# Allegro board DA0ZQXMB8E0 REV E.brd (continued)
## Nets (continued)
Pads without a net: C6 2; C7 1 2; C9 2; C10 1; C11 1; C12 1; C13 1; C15 1 2; C16 1; C17 2; C18 1; C19 1 2; C20 1 2; C21 1; C23 1 2; C28 1 2; C31 1; C32 1; C33 2; C40 1 2; C80 2; C82 1 2; C84 1 2; C110 2; C111 1 2; C122 1 2; C123 1 2; C124 1 2; C125 1 2; C126 1 2; C127 1 2; C128 1 2; C129 1 2; C130 1 2; C131 1 2; C132 1 2; C133 1 2; C134 1 2; C135 1 2; C136 1 2; C137 1 2; C138 1 2; C139 2; C140 1 2; C141 1 2; C142 1 2; C143 1 2; C144 1 2; C145 1 2; C146 1 2; C147 1 2; C148 1 2; C152 1 2; C153 1 2; C154 1 2; C156 1 2; C157 1; C158 1 2; C160 1 2; C161 2; C162 2; C163 2; C164 1 2; C165 1 2; C166 2; C167 1 2; C168 1 2; C169 1 2; C170 1; C171 1; C172 1 2; C173 1 2; C174 1 2; C175 2; C176 2; C177 2; C178 1 2; C182 1 2; C183 1 2; C185 1 2; C186 1 2; C187 1 2; C188 2; C189 1; C190 1 2; C191 1 2; C192 1; C193 1; C194 1 2; C195 2; C197 2; C198 2; C199 1 2; C200 1 2; C201 1 2; C203 2; C204 1 2; C205 1 2; C206 2; C207 1 2; C208 2; C209 1 2; C210 1; C211 1 2; C212 1 2; C213 1 2; C214 1 2; C215 1 2; C216 1 2; C217 1 2; C218 1 2; C219 1 2; C220 1 2; C221 1 2; C222 1 2; C223 1 2; C224 2; C225 1 2; C226 2; C227 1 2; C228 1 2; C229 2; C230 2; C231 2; C232 2; C233 1 2; C234 2; C235 2; C236 2; C237 2; C238 2; C239 2; C240 1 2; C241 1 2; C242 2; C243 2; C244 1 2; C245 2; C246 1 2; C247 2; C248 2; C249 1 2; C250 2; C251 1 2; C252 2; C253 2; C254 2; C255 2; C256 2; C257 2; C258 1 2; C259 2; C260 2; C261 1 2; C262 2; C263 1 2; C264 2; C265 2; C266 2; C267 2; C268 2; C269 2; C270 1 2; C271 2; C272 1 2; C273 1 2; C274 2; C275 1 2; C276 1 2; C277 1 2; C278 1 2; C279 2; C280 1 2; C281 1; C282 2; C284 1 2; C285 2; C286 1 2; C287 1 2; C288 1 2; C289 1 2; C290 1 2; C291 1 2; C292 1; C293 1 2; C294 1; C295 1 2; C296 1 2; C297 1 2; C298 1 2; C299 2; C300 2; C301 2; C302 2; C305 2; C306 2; C307 2; C308 2; C309 1; C310 1 2; C311 1 2; C312 2; C313 1 2; C314 1 2; C315 1 2; C316 1 2; C317 1 2; C318 1 2; C319 1; C320 1; C322 2; C323 2; C324 1; C325 2; C326 2; C328 2; C329 2; C330 2; C331 2; C332 2; C333 1; C334 2; C335 1 2; C336 2; C337 1 2; C338 2; C339 1; C340 1; C341 1 2; C342 1 2; C343 1 2; C344 1 2; C345 1; C346 2; C347 1 2; C348 1 2; C349 2; C350 1 2; C351 1 2; C352 1 2; C353 2; C354 1; C356 2; C357 1 2; C358 1 2; C359 2; C360 1 2; C369 1; C370 1; C371 1 2; C372 1 2; C373 1 2; C374 1 2; C376 1 2; C391 1; C392 1; C394 1; C398 2; C404 1 2; C405 1 2; C407 1 2; C408 1 2; C409 1 2; C410 1 2; C411 1 2; C412 2; C415 1 2; C419 2; C420 1; C421 2; C422 1 2; C425 1 2; C426 1 2; C427 2; C428 2; C429 1 2; C430 1 2; C431 1 2; C432 2; C433 1 2; C434 1 2; C435 1 2; C436 2; C437 1; C438 1; C439 1 2; C440 1 2; C441 1 2; C442 1 2; C443 1 2; C444 1 2; C445 1 2; C447 2; C448 1; C449 2; C450 1; C451 2; C452 1 2; C453 1 2; C456 1 2; C457 2; C458 1 2; C459 1 2; C462 2; C463 1; C464 2; C465 1 2; C466 2; C469 1 2; C470 1 2; C471 1 2; C472 1 2; C473 1 2; C474 1; C475 1 2; C476 1; C477 1 2; C478 2; C479 1 2; C480 1; C481 1; C482 1 2; C483 1 2; C484 1 2; C485 1 2; C486 1 2; C487 1 2; C488 1 2; C489 2; C490 2; C491 1 2; C492 1 2; C493 1 2; C494 1 2; C495 1 2; C496 1 2; C498 1 2; C499 1 2; C500 1 2; C501 1 2; C502 1 2; C503 1 2; C504 1 2; C505 1 2; C507 1 2; C508 1 2; C509 1 2; C510 1 2; C511 1 2; C512 1 2; C513 1 2; C514 1 2; C515 1 2; C516 1 2; C517 1 2; C518 1 2; C519 1 2; C520 1 2; C522 1 2; C523 2; C524 1 2; C525 1; C526 1 2; C527 2; C528 1 2; C529 1 2; C530 1 2; C531 1 2; C532 1 2; C533 1 2; C534 2; C535 2; C536 1 2; C537 1 2; C538 1 2; C539 1 2; C540 1 2; C541 1 2; C542 1 2; C543 1 2; C544 1 2; C545 1 2; C546 1 2; C547 2; C548 1 2; C549 1 2; C550 1 2; C551 1; C553 1 2; C554 1 2; C555 2; C556 1 2; C557 1 2; C558 1 2; C559 2; C560 1 2; C561 1 2; C562 1 2; C563 1 2; C564 1 2; C565 1 2; C566 2; C567 2; C568 2; C569 1; C570 2; C571 1; C572 1; C573 1 2; C576 1 2; C577 1; C578 1; C579 1 2; C580 1 2; C581 1 2; C582 1 2; C692 1 2; CN6 1 4 5 6 9 10 12 15 18 21 24 25 26 27 30 31 34 36 39 40 43 46 49 51 52 54 55 56 58 59 60; CN7 1 2 3 5 6 7 9 12 15 24 25 28 29 37 38 39 40 41 42 43 44; CN8 1 2 3 5 7 9 18 19 20 23 24 25 26 27 28 29 30 31 32 33 34 35 36 37 38 39 40 41 43 45; CN10 5; CN11 1 2 3 4 5 6 7 8 9 12 14 15 18 19 20 22 24 25 26 30 31 32; CN12 11 12; CN13 1 2 3 4 5 6 7 10; CN14 3 4 5 6 7 8 9 11 12 13 14 15 16 17 20 21 23 24 26 27 28; CN15 3 5; CN17 1 4 9 10; CN18 2 5 11 17 20 21 22 23; CP6 1 2 3 4 5 7 8; CP7 1 3 4 5 6 7; CP8 1 2 3 4 5 6 7; CP9 1 2 3 4 5 6 7 8; CP10 1 2 3 4 5 6 7; CP11 1 2 3 4 5 6 7 8; D6 1; D7 1 2; D8 1 2; D9 1; D11 1; D13 1; D14 1; D15 1; D16 1; D17 2; D19 2; D20 1; D21 2; D22 1 2; D23 1 2; D24 1 2; D25 2; D26 2; D27 1 2; D28 1 2; HOLE7 1 2 3 4 5 6 7 8 9; HOLE10 2 3 4 5 6 7 8 9; HOLE15 5 7; HOLE16 5 7; HOLE17 5 7; JDIM6 3 8 9 11 13 19 31 37 43 49 55 76 82 88 100 106 112 118 122 124 128 134 136 138 144 150 156 161 167 168 173 178 179 184 185 187 189 195 196 199 200 203 204 205 206; JP6 1 2; JP7 2; JP8 1; JP9 1 2; JP11 2; JP12 1 2; JP13 2; JP14 1 2; JP15 2; JP16 2; JP17 1 2; JP18 1 2; L6 2; L9 1; L10 1; L11 1 2; L12 1 2; L15 1 2; L16 1; L17 1; L18 1; L19 1; L21 1 2; L22 1 2; MR6 2 3; PC6 1 2; PC7 1 2; PC8 1 2; PC9 2; PC11 1 2; PC12 1 2; PC13 2; PC14 2; PC15 1 2; PC16 2; PC17 2; PC18 1 2; PC19 1 2; PC20 1 2; PC21 2; PC22 1; PC23 1; PC24 1; PC25 1; PC26 1; PC27 1; PC29 1 2; PC30 1 2; PC31 2; PC32 1; PC34 1; PC35 2; PC37 1 2; PC38 1 2; PC41 2; PC42 1 2; PC43 2; PC44 1 2; PC47 2; PC49 1 2; PC52 1 2; PC53 2; PC55 1 2; PC58 1; PC59 2; PC60 2; PC61 1 2; PC62 1; PC64 2; PC65 2; PC66 2; PC67 1; PC68 1 2; PC69 2; PC70 2; PC73 2; PC74 1 2; PC76 1 2; PC77 2; PC78 2; PC82 1 2; PC83 1 2; PC86 1 2; PC87 2; PC88 1; PC90 2; PC91 1 2; PC92 1 2; PC93 1 2; PC95 2; PC97 2; PC98 2; PC99 1 2; PC100 2; PC101 2; PC102 2; PC103 1; PC104 2; PC105 1 2; PC107 1 2; PC109 1 2; PC110 1 2; PC111 1; PC112 1; PC113 1 2; PC114 1; PC115 2; PC116 2; PC117 2; PC119 2; PC121 2; PC122 2; PC123 2; PC126 1 2; PC128 1; PC129 1 2; PC130 2; PC132 1; PC133 2; PC134 1 2; PC135 1; PC136 1; PC137 1 2; PC139 2; PC140 1 2; PC141 2; PC142 2; PC144 1 2; PC145 1 2; PC146 1 2; PC147 1; PC149 2; PC150 1; PC151 2; PC153 2; PC154 1 2; PC155 2; PC157 2; PC158 2; PC159 2; PC160 1; PC161 1; PC162 2; PC163 2; PC164 1 2; PC168 1 2; PC169 1 2; PC170 1 2; PC171 1; PC172 1; PC173 1; PC174 1 2; PC176 1 2; PC177 2; PC178 1; PC180 2; PC181 2; PC182 1 2; PC183 1; PC185 2; PC186 1; PC187 2; PC188 1; PC189 1 2; PC190 1 2; PC191 1 2; PC192 1; PC193 1 2; PC194 1 2; PD6 1 2; PD8 1 2 3; PD9 1; PD10 2 3; PJ6 3; PL7 1 2; PL10 1; PL11 1 2; PL12 1 2; PL13 2 4; PL16 2; PQ6 1 2; PQ7 1 3; PQ8 1 2 3; PQ9 1 2 3; PQ10 1 2 3; PQ11 1 2 3; PQ12 1 2; PQ13 1 2 3; PQ14 1 3; PQ15 1 2; PQ16 1 3; PQ17 1 2 3; PQ18 1 2 3; PQ19 1 2 3; PQ20 1 3; PQ21 1; PQ22 1 2; PQ23 1 3; PQ24 3; PQ25 1 3 4 5; PQ26 1 3 4 5; PQ27 1; PQ28 1 3; PQ29 1; PQ30 1 2; PQ31 1; PQ32 1 2 3 4 5; PQ33 1; PQ34 1 2 3 5; PQ35 1 3; PQ36 1 2 3 4 5; PQ37 1 2 3 4 5; PQ38 1 3; PQ39 1 2 3 4 5; PQ40 1 3 4; PQ41 1 3 4 5; PQ42 1 3 4 5; PQ43 1 2 3; PQ44 1 3; PQ45 1 2; PQ46 1 2; PQ48 1 3 4 5; PQ49 1 3 4 5; PQ50 1 3; PQ51 5; PQ52 1 3; PQ53 1 4; PR6 2; PR8 1; PR9 2; PR10 1 2; PR11 1 2; PR12 2; PR13 1 2; PR16 2; PR17 2; PR18 1 2; PR20 1; PR21 2; PR22 1 2; PR23 1 2; PR24 1 2; PR25 1 2; PR26 1 2; PR28 1 2; PR29 1 2; PR30 1 2; PR31 1 2; PR32 1 2; PR33 1 2; PR34 1 2; PR35 1 2; PR37 2; PR38 2; PR39 1; PR40 1 2; PR41 1 2; PR42 1 2; PR43 1 2; PR44 1; PR45 1; PR46 1 2; PR47 1 2; PR48 2; PR49 1; PR50 1 2; PR51 2; PR53 1 2; PR54 1; PR55 1 2; PR56 1; PR57 1 2; PR58 1; PR62 2; PR63 1 2; PR64 1; PR68 1; PR69 1; PR73 1; PR76 1 2; PR80 2; PR81 2; PR83 1; PR84 2; PR85 2; PR86 2; PR91 2; PR93 1; PR94 1; PR95 2; PR96 2; PR97 1; PR98 2; PR99 2; PR101 1; PR102 2; PR103 1; PR104 1 2; PR105 2; PR107 1; PR108 1; PR109 1; PR110 2; PR113 1 2; PR114 1 2; PR115 1 2; PR116 1; PR117 1; PR118 2; PR119 1 2; PR120 1 2; PR121 1; PR128 2; PR130 2; PR131 1; PR134 1; PR137 2; PR138 2; PR139 2; PR140 1; PR141 2; PR143 1 2; PR147 1 2; PR153 1 2; PR156 1; PR159 2; PR160 1 2; PR161 1; PR163 1 2; PR169 1 2; PR170 1 2; PR171 1 2; PR172 2; PR173 1; PR174 1 2; PR175 1; PR177 1 2; PR178 1 2; PR179 1; PR180 1; PR181 1; PR183 2; PR184 1; PR185 2; PR198 1; PR199 2; PR202 1 2; PR205 2; PR206 1; PR208 2; PR213 2; PR215 1; PR218 2; PR220 2; PR225 2; PR226 1; PR228 1; PR229 2; PR230 1; PR232 2; PR233 2; PR234 1 2; PR235 1 2; PU6 1 6 9 10 11 13 14 15 20; PU7 21 22 33 34 35 37 38 40 41 42; PU10 2 3 5 6 8 12 13 14 15 16; PU13 4 6; PU16 1 2 5 6 11; PU17 2 14; PU18 1 5 6; Q6 2 5 6; Q8 1 3; Q9 1; Q10 1 4 6; Q12 1 2; Q13 1 2 3; Q14 2 3 5 6; Q15 1 2; Q17 2 4 5; Q18 1; Q19 2; Q20 1; Q21 2 3; Q22 1; Q23 2; Q24 2; Q25 2; Q26 1 4 6; Q27 2 3; Q28 2; Q30 1; Q33 1 2 3; Q35 1 2 3; Q38 1; Q40 1 3; Q41 3; Q42 3; Q43 3; Q44 2 5; Q45 1 2; R7 1 2; R9 2; R10 1 2; R11 2; R30 1 2; R38 2; R39 1; R40 1 2; R42 2; R47 1; R48 1 2; R49 1 2; R56 1 2; R59 1 2; R60 1; R61 1 2; R64 1 2; R65 2; R67 1; R69 1; R78 1; R82 1 2; R83 1; R87 2; R88 1 2; R89 1 2; R91 1; R92 1; R93 2; R94 2; R95 1; R96 2; R97 1; R98 1; R99 1 2; R101 1 2; R102 1; R103 1; R104 1 2; R105 1; R106 2; R107 1 2; R108 1 2; R109 1 2; R110 1 2; R111 1 2; R112 1 2; R113 1; R114 1; R115 1 2; R116 1 2; R117 2; R118 1; R119 1; R120 1 2; R121 1; R122 1 2; R123 1; R124 1; R126 1; R127 1 2; R128 1; R129 1; R134 2; R135 1 2; R137 1 2; R140 2; R141 2; R142 2; R143 1; R144 2; R145 1 2; R146 1; R147 2; R148 1 2; R149 1; R150 1 2; R151 2; R152 2; R153 2; R154 1; R155 1 2; R156 1; R157 2; R158 2; R159 2; R160 2; R161 1; R162 2; R163 1; R164 2; R165 2; R166 2; R167 1; R168 2; R169 1 2; R170 1 2; R171 2; R172 1; R173 1; R174 1; R176 2; R177 1 2; R178 2; R179 1 2; R180 2; R181 2; R182 2; R183 2; R184 2; R185 1 2; R186 2; R187 2; R188 2; R189 2; R190 2; R191 2; R192 2; R193 1 2; R197 2; R198 2; R199 2; R200 2; R201 2; R202 1; R205 2; R206 2; R207 1 2; R208 1 2; R211 2; R213 1; R214 1 2; R215 1 2; R217 1; R218 1; R219 1; R220 1; R222 2; R223 1; R224 1; R225 1; R230 1; R231 1 2; R232 2; R233 2; R234 1; R235 2; R236 1; R237 1; R238 2; R239 1 2; R242 1; R246 1 2; R247 1 2; R248 1; R249 1; R250 2; R251 1 2; R252 2; R253 1 2; R254 1; R255 2; R257 1; R258 1; R259 1; R260 1; R261 1 2; R262 1 2; R263 2; R264 1 2; R265 1 2; R266 1 2; R268 1; R269 1 2; R270 1 2; R271 1; R272 1; R273 1; R274 1; R275 2; R276 1 2; R277 1; R281 1; R284 1; R286 2; R288 1; R289 1; R290 2; R291 2; R292 2; R293 1; R294 2; R295 1; R296 1 2; R297 1; R300 1; R301 1; R302 2; R303 1; R306 2; R307 2; R308 2; R309 1; R310 1 2; R311 2; R313 1; R315 1 2; R316 2; R317 2; R318 1 2; R319 2; R320 1; R322 1; R328 1; R329 1; R330 1; R331 2; R332 2; R333 1 2; R334 2; R336 2; R345 1 2; R366 2; R369 1; R370 1; R371 1 2; R375 1 2; R376 2; R377 2; R378 2; R382 1 2; R383 1 2; R385 1 2; R386 1; R388 1 2; R389 1 2; R390 1 2; R391 1 2; R393 1 2; R394 1 2; R395 2; R396 2; R401 2; R404 1 2; R405 1 2; R406 1 2; R407 1 2; R408 1 2; R411 1 2; R412 1 2; R413 1 2; R414 2; R417 1 2; R420 1 2; R422 1; R423 1; R424 1 2; R425 1 2; R426 1; R427 1; R428 1; R433 2; R434 2; R435 1 2; R436 1; R437 1 2; R438 1 2; R439 1 2; R440 1 2; R441 1; R442 2; R443 1 2; R444 2; R445 2; R446 2; R448 1 2; R449 1 2; R451 1; R452 1 2; R453 2; R454 2; R455 1; R456 2; R457 1 2; R458 2; R459 2; R460 2; R461 1; R462 2; R463 1; R464 2; R465 1 2; R466 1; R467 2; R469 1; R470 2; R471 2; R472 1; R473 1 2; R474 1; R475 1 2; R476 1 2; R477 1; R478 2; R479 2; R480 1; R483 2; R485 1; R486 2; R487 2; R488 2; R489 2; R490 1; R491 2; R492 2; R493 1; R494 2; R495 2; R496 1; R497 2; R498 2; R499 1 2; R500 1; R501 1; R502 2; R503 1; R504 2; R505 2; R506 2; R507 1 2; R509 1; R510 2; R512 2; R514 1; R515 2; R517 2; R518 2; R519 1 2; R520 1; R522 1; R523 2; R525 2; R527 2; R528 1; R530 1; R531 2; R533 1; R534 2; R536 1; R537 1 2; R541 1; R543 1; R547 1; R549 1; R550 1; R552 1; R553 1; R554 1 2; R555 1 2; R556 2; R557 1 2; R558 2; R559 1 2; R560 1 2; R561 1 2; R562 2; R564 1 2; R565 2; R566 1; R567 2; R568 1 2; R570 1 2; R571 1; R573 1; R576 2; R577 1 2; R578 2; R579 2; R580 1 2; R582 2; R583 1 2; R585 1; R586 1; R587 1 2; R588 2; R593 2; R594 1 2; R595 2; R596 2; R597 2; R599 1 2; R600 1 2; R603 1 2; R604 1; R609 2; R610 1 2; R611 1; R613 2; R614 2; R615 1; R616 1; R617 2; R619 2; R621 2; R623 1; R625 2; R627 2; R631 2; R632 1 2; R633 1 2; R635 2; R650 2; R653 2; RP6 1 2 3 4 5 8 9 10; RP7 3 4 5 6 7 8 9 10; RV6 2; SW7 2 3; TP18 1; TP72 1; TP76 1; TP77 1; TP83 1; TP90 1; TP101 1; TP102 1; TP105 1; U6 2 4 5 6; U7 2 3 4 5; U8 1 3 4 8 10 11 12 13 14 15 18 19 22 24 25 26 28; U9 3 5; U10 4; U12 A1 A7 A8 A9 B1 B2 J8 J9 K1 K2 K3 K7 K8 L1 L2 L3 L7 L9 M1 M2 M3 R2 R3 R9 T1 T2 T3 T7 T9; U13 A1 A8 A9 B1 B2 J8 J9 K1 K2 K3 K7 K8 L1 L2 L3 L7 L9 M1 M2 M3 R2 R3 R9 T1 T2 T3 T7 T9; U14 A1 A8 A9 B1 B2 J8 J9 K1 K2 K3 K7 K8 L1 L2 L3 L7 L9 M1 M2 M3 R2 R3 R9 T1 T2 T3 T7 T9; U15 A1 A3 A8 A9 B1 B2 J8 J9 K1 K2 K3 K7 K8 L1 L2 L3 L7 L9 M1 M2 M3 R2 R3 R9 T1 T2 T3 T7 T9; U16 4 6 10 14 15; U17 2 3 4 5 11 12 14 15 16 18 20 23 24 25 26 30 38 41 42 43 44 45 46 48 49; U18 1 2 3 4; U19 1 2 3 4 5; U24 4 5 6; U25 1 2 4 6 10 68 69 70 71 100 125 127 128; U26 A1 A3 A8 A9 B1 B2 J8 J9 K1 K2 K3 K8 L1 L2 L3 L7 L9 M1 M2 M3 R2 R3 R9 T1 T2 T3 T7 T9; U27 A1 A8 A9 B1 B2 J8 J9 K1 K2 K3 K8 L1 L2 L3 L7 L9 M1 M2 M3 R2 R3 R9 T1 T2 T3 T7 T9; U28 A3 A4 A24 A28 A36 A44 A47 AA1 AA63 AC2 AC61 AC62 AD63 AE5 AE8 AF1 AF9 AG1 AH28 AH42 AH44 AH46 AJ43 AJ45 AJ47 AK23 AK62 AK63 AL1 AL17 AL26 AL45 AL46 AM1 AM52 AN36 AN39 AN40 AN42 AN43 AN45 AN46 AP1 AP36 AP38 AP39 AR5 AR15 AR48 AT1 AT2 AT13 AT43 AT46 AU1 AU12 AU43 AU44 AV2 AV3 AV8 AV10 AV42 AV43 AV44 AW2 AW3 AW4 AW33 AW34 AW37 AW39 AW42 AW43 AW49 AW50 AW51 AW53 AY2 AY3 AY4 AY6 AY8 AY26 AY33 AY40 AY41 B24 B26 B28 B37 B43 C1 C24 C25 C27 C28 C33 C39 C45 C46 C47 C48 D2 D5 D6 D8 D9 D17 D18 D21 D23 D25 D26 D27 D43 D47 E5 E17 E18 E23 E25 E27 E43 E45 E47 F8 F18 F22 F24 F26 F28 F42 F46 F48 F62 G3 G5 G6 G8 G22 G23 G25 G27 G43 G45 G47 H5 H6 H22 H23 J3 J4 J5 J6 J11 J22 J23 K1 L61 N3 N5 P2 P62 P63 R6 R7 R8 T1 U8 U61 V1 V2 Y2 Y63; U29 A1 A8 A9 B1 B2 J8 J9 K1 K2 K3 K8 L1 L2 L3 L7 L9 M1 M2 M3 R2 R3 R9 T1 T2 T3 T7 T9; U30 15 16 21 22; U31 1 2 5; U32 A1 A2 A8 A9 B1 B2 J8 J9 K1 K2 K3 K8 L1 L2 L3 L7 L9 M1 M2 M3 R2 R3 R9 T1 T2 T3 T7 T9; U33 1 5; U34 2; U35 2; U36 28 29 31 32 33; U37 1 5; U38 3 5; U39 1 2 5; U40 1 2 3 6 7 8; Y7 2 3; Y8 2 4; Y9 1 2 3 4

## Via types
v1: diameter 0.508, hole 0.254, TOP to BOTTOM, 78 vias
v2: diameter 0.61, hole 0.356, TOP to BOTTOM, 21 vias
v3: diameter 0.66, hole 0.33, TOP to BOTTOM, 16 vias
v4: diameter 0.66, hole 0.254, TOP to BOTTOM, 19 vias

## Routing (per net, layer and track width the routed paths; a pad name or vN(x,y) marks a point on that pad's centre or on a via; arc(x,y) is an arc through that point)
5VPCU_AGND: length 1.3
  TOP w0.381: PC63.1 58.37,44.15 58.72,44.49
  BOTTOM w0.203: PU16.14 55.57,44.96 55.77,44.76 55.85,44.76 55.9,44.71 55.92,44.71 55.97,44.65 56,44.65 56.02,44.63
+1.05V_DCPSUS1: length 0.6
  TOP w0.102: C231.1 131.14,82.31
+1.05V_DCPSUS2: length 1.3
  TOP w0.254: C232.1 R238.1
+1.5VA: length 1.7
  TOP w0.508: 228.71,54.5 228.72,54.51 C302.1 C301.1
+3V_PCH_ME: length 2.3
  BOTTOM w0.508: 142.84,118.65 142.84,120.32 142.75,120.41 C420.2
+3V_RTC: length 3.2
  BOTTOM w0.508: 218.43,125.55 220.15,125.55 C412.1 ; C447.1 R526.1
+A3VPCU: length 2.9
  BOTTOM w0.203: 201.82,116.17 200.58,116.17
  BOTTOM w0.508: L17.2 198.24,117.11 C424.1
+V1.05S_AIDLE: length 1.2
  BOTTOM w0.254: 126.87,95.48 v1(126.87,96.15) 126.62,96.15 U28.N8
  vias: v1(118.81,100.69) v1(119.5,100.69)
+V1.05S_APLLOPI:
  vias: v1(104.62,91.14) v1(104.99,91.64) v1(129.78,88.28) v1(130.6,88.28)
+V1.05S_ASATA3PLL: length 5.8
  BOTTOM w0.178: 118.36,93.78 119.3,93.78 119.33,93.82 119.75,93.82
  BOTTOM w0.254: 118.36,93.78 118.23,93.78 118.08,93.93 116.12,93.93 115.51,94.54 115.51,94.87 115.1,95.29 R539.2
+V1.05S_AXCK_LCPLL: length 4
  BOTTOM w0.254: 118.51,89.69 118.51,89.59 119.11,88.99
  BOTTOM w0.508: 118.51,89.69 118.51,89.79 116.45,91.85
+V3.3M_PSPI: length 3
  BOTTOM w0.254: 130.21,95.93 130.44,95.93 130.66,96.15
  BOTTOM w0.381: 104.51,102.36 R522.2 106.16,103.13
+V3.3S_VCCPCORE:
  vias: v1(111.62,101.93) v1(112.08,103.02) v1(112.08,102.36) v1(129.71,94.56)
+V3.3S_VCCPTS: length 1.7
  TOP w0.381: C208.1 100.08,90.84 99.69,91.24
+VCCIOA_OUT: length 0.6
  BOTTOM w0.254: U28.E20 121.96,89.1 121.96,88.8
VSS_SENSE: length 1.4
  TOP w0.254: PC43.1 72.06,64.73 72.08,64.75 PR97.2
671_SW:
  vias: v2(53.13,53.01) v2(53.15,52.12) v2(53.18,50.93) v2(53.18,49.86) v2(53.23,48.8) v2(54.09,53.93) v2(54.17,48.82) v2(54.83,54.43) v2(55.08,48.82)
671PG: length 1.8
  BOTTOM w0.203: PU16.4 51.67,45.55 51.08,46.14 51.08,46.15
24737_BM#: length 1.6
  TOP w0.305: 78.07,46.72 77.56,46.2 PQ31.2
24737_BST: length 2.6
  BOTTOM w0.279: 84.34,44.35 84.34,44.6 83.79,45.16 82.96,45.16 82.9,45.1 PU17.17
24737_DH: length 1.1
  BOTTOM w0.279: PU17.18 83.13,44.6 83.18,44.55 83.33,44.55
24737_DL: length 1.1
  BOTTOM w0.508: PQ50.4 87.18,50.66 86.85,50.32 86.81,50.32
24737_VCC: length 0.5
  BOTTOM w0.279: PC188.2 83.86,41.81
51216_REFIN: length 0.7
  TOP w0.208: PC33.1 229.32,76.25 228.79,76.25
51624_ALERT#: length 2
  TOP w0.198: PU7.32 79.9,61.05 80.23,60.73 PR108.2
51624_CLK: length 2
  TOP w0.198: PR107.2 79.5,60.57 PU7.31
51624_CSN2: length 1
  BOTTOM w0.198: PC156.2 PR204.2
51624_CSP1: length 1.2
  BOTTOM w0.198: PC152.1 74.12,68.24 73.91,68.02 73.33,68.02 PR201.1
51624_CSP2: length 2.4
  BOTTOM w0.198: PC156.1 PR204.1
  BOTTOM w0.305: PC157.1 72.21,65.51 72.98,65.51 PC156.1
51624_DROOP: length 5
  TOP w0.198: PU7.25 76.76,62.19 76.52,61.95
  TOP w0.305: 74.16,59.33 74.39,59.1 PC50.1 ; PC46.1 76.52,61.95
  TOP w0.381: PC50.1 75.09,58.9 PR111.1
51624_PWM1_R: length 0
  BOTTOM w0.198: 83.56,69.12 83.56,69.17
+AZA_VDD: length 1.4
  TOP w0.508: R256.1 v1(219.96,59.72)
+SMDDR_VREF_DIMM: length 5.1
  BOTTOM w0.508: C464.1 174.24,90.98 177.38,94.13
+SMDDR_VREF_DQ1:
  vias: v1(161.92,49.56) v1(162.55,49.56)
BATLED1#: length 1.8
  BOTTOM w0.203: 217.52,115.37 215.87,115.37 215.85,115.39
  BOTTOM w0.254: 215.85,115.39 215.75,115.5
BL#: length 4.1
  TOP w0.102: Q10.3 93.35,138.19 92.7,138.84 R65.1 93.09,139.21 93.46,138.84 Q10.2
CATERR#: length 3.2
  TOP w0.102: 125.14,61.16 124.5,61.16 TP49.1
CCD_PWR:
  vias: v1(76.95,150.34) v1(77.59,150.34)
CFG_RCOMP: length 1.5
  BOTTOM w0.203: 129.2,60.52 129.07,60.65 129.07,61.46 129.28,61.67 129.28,61.89
CL_DAT: length 8.9
  BOTTOM w0.076: U28.AD2 132.61,100.16 132.61,100.7 132.37,100.94 132.37,101.43 132.38,101.45 132.5,101.58
  BOTTOM w0.102: TP96.1 133.67,107.55 133.37,107.24 133.37,104.37 132.86,103.86 132.86,102.03 132.5,101.68 132.5,101.58
CLK_PCIE_LANN:
  vias: v1(32.96,44.67)
CLK_PCIE_LANP: length 2.4
  BOTTOM w0.102: 120.08,75.21 118.23,75.21 117.85,75.59
  vias: v4(32.96,45.43)
CS_BST2: length 2.7
  BOTTOM w0.198: PC165.1 85.51,60.89 85.94,61.32 86.52,61.32 86.8,61.6 86.8,62.11
CS_BSTR1: length 0
  BOTTOM w0.198: 87.08,71.33 87.08,71.32
CS_BSTR2: length 2.1
  BOTTOM w0.198: PR207.2 86.73,60.94 87.2,61.41 87.2,62.11
D/C#: length 1.4
  BOTTOM w0.102: 207.47,126.62 207.47,125.37 207.59,125.25
DDR_PG_CTRL: length 5.9
  BOTTOM w0.076: 140.16,63.21 140.09,63.15 140.09,62.04 140.11,62.02 140.11,59.66 141.75,58.02
DDR_VTTT_PG_CTRL: length 5.3
  BOTTOM w0.102: 152.56,55.88 149.93,55.88 149.72,56.08 149.72,56.67 ; 146.07,57.19 147.55,57.19 147.81,56.93
DGPU_OTP#: length 4.5
  BOTTOM w0.102: 201.82,116.97 201.05,116.97 200.7,117.32 200.7,117.96 198.87,119.79
E51_TXD: length 4.2
  BOTTOM w0.102: 208.27,126.62 208.27,127.34 208.08,127.54 207.05,127.54 TP81.1
EC_FPBACK#: length 2.7
  TOP w0.102: 97.58,139.7 97.12,140.16 Q8.2
  BOTTOM w0.102: 211.87,126.62 211.87,127.65 212.01,127.79
ECAGND: length 4.4
  BOTTOM w0.203: 201.82,116.57 201.02,116.57 200.17,117.43
  BOTTOM w0.508: C423.1 198.21,118.36 L16.2 ; 200.17,117.43 199.7,117.89 C424.2
EDP_AUX#_C: length 2.9
  TOP w0.102: R42.1 84.21,148.77 85.56,148.77 C21.2
EDP_TX1#_C: length 0.6
  BOTTOM w0.102: C392.2 83.86,145.91
EDP_TX1_C: length 0.5
  BOTTOM w0.102: C391.2 83.66,145.81
EDP_TXP0: length 3
  BOTTOM w0.102: 119.71,72.49 119.86,72.65 120.03,72.65 120.08,72.7 ; C393.1 86.25,144.26 86.25,142.7 86,142.44
EDP_VDD_EN: length 4.5
  BOTTOM w0.102: 116.04,96.85 116.32,97.13 119.24,97.13 119.64,96.74 120.3,96.74
EDP_VDD_EN_R: length 2.9
  TOP w0.102: R78.2 95.14,133.31 ; U6.3 97.47,133.95 96.83,133.31
FAN1_PWM: length 2.1
  BOTTOM w0.102: 218.81,113.47 218.75,113.41 218.75,112.72 218.61,112.57 217.52,112.57
GPIO65: length 0.6
  BOTTOM w0.102: v1(122.18,98.89) 122.51,98.56 U28.F4
GPP_TX2P_LAN: length 4.8
  BOTTOM w0.102: U36.17 31.49,48.03 31.39,48.13 31.08,48.13 30.66,47.7 v3(30.66,46.93) 30.32,47.27 30.17,47.27 30.02,47.13 29.59,47.13 29.23,46.76 29.23,46.64 29.34,46.52 C575.1
H_CPU_SVIDART#: length 2.3
  TOP w0.102: 124.71,57.17 124.3,56.77 122.91,56.77 R263.1
H_CPU_SVIDCLK: length 6.2
  BOTTOM w0.076: 126.15,59.49 126.15,61.75 U28.N63
  BOTTOM w0.102: 126.15,59.49 126.15,58.14 125.76,57.75 125.76,57.44 124.71,56.38
H_PECI: length 14.5
  BOTTOM w0.102: 128.19,49.56 126.08,51.67 126.08,54.38 126.36,54.66 126.36,59.15 126.47,59.26 126.47,61.61 126.6,61.74 126.6,62.22 U28.N62 ; v1(131.65,48.16) 131.65,48.42
HDMI_5V:
  vias: v1(15.08,37.16) v1(15.13,37.8)
HDMI_DDCCLK_SW: length 5.3
  TOP w0.102: v1(26.45,42.32) 26.18,42.05 25.79,42.05 R314.2
  BOTTOM w0.102: 119.75,94.8 119.64,94.69 119.02,94.69 118.3,95.4 117.19,95.4 116.98,95.2 116.98,94.92 v1(116.73,94.67)
HP_DET_CN: length 6.2
  TOP w0.102: 11.19,38.05 8.34,35.2 CN18.19 ; RV6.1 13.44,43.44 R305.1
HPR: length 2.1
  IN3 w0.508: 226.43,36.5 226.94,37.01 228.34,37.01
  vias: v1(231.28,50.09)
HWPG: length 0.9
  TOP w0.102: D9.2 200.91,125.24
HWPG_1.05V_S5: length 2.7
  TOP w0.102: D10.1 202.94,126.37 203.17,126.14 204.02,126.14 204.68,125.47
I2C1_SCL_GPIO7: length 4.7
  BOTTOM w0.102: 48.58,40.39 48.58,39.35 48.38,39.14 48.38,38.89 47.98,38.49 Q44.4 46.97,38.49 46.83,38.36 46.83,37.38 R634.2
I2C_TP_SCL_R: length 3.5
  BOTTOM w0.102: 50.16,38.35 50.02,38.49 Q44.3 48.72,38.49 48.53,38.3 48.53,37.26 48.38,37.11 R634.1
I2C_TP_SDA_R: length 0.7
  BOTTOM w0.102: Q44.6 47.94,39.79 48.05,39.91
ICMNT: length 1.3
  BOTTOM w0.102: 195.57,119.08 195.77,119.28 C423.2
INT_HDMITX1N: length 2.5
  BOTTOM w0.102: 120.08,65.18 119.94,65.18 119.91,65.2 117.95,65.2 117.72,65.43
INT_HDMITX1N_C: length 1.4
  TOP w0.102: C363.2 13.8,32.89 13.36,32.89 R325.2
INT_HDMITX2P_C: length 8
  TOP w0.102: CN18.1 7.93,26.56 8.04,26.56 8.75,25.85 9.82,25.85 10.46,26.49 10.46,27.15 11.68,28.37 11.85,28.37 12.13,28.09 ; C368.2 13.8,28.37 13.36,28.37 R327.1
L_SPK-_1:
  vias: v3(204.03,46.59)
LCDVCC:
  vias: v1(75.43,148.06) v1(76.04,148.01) v1(76.67,148.01)
LPC_LAD2: length 3.8
  BOTTOM w0.102: 214.52,120.17 216.52,122.17 U25.8
LPC_LAD3: length 53.1
  TOP w0.102: U8.17 216.32,122.99 216.22,123.09 214.92,123.09 213.82,121.99
  BOTTOM w0.076: 143.44,94.93 142.95,94.43 141.59,94.43 141.3,94.14 U28.AW11
  BOTTOM w0.102: 161.89,117.87 158.29,114.27 158.29,113.5 157.32,112.53 157.32,103.92 155.54,102.14 155.54,100.32 155.18,99.96 155.18,99.81 155.54,99.45 155.54,99.28 155.42,99.16 155.25,99.16 154.89,99.53 154.75,99.53 154.6,99.38 154.6,99.24 155.2,98.64 155.2,98.47 155.08,98.35 154.92,98.35 154.31,98.95 154.17,98.95 154.03,98.81 154.03,98.66 154.68,98.01 154.68,97.84 154.56,97.72 154.39,97.72 153.74,98.38 153.6,98.38 153.45,98.23 153.45,98.09 154.08,97.46 154.08,97.29 153.96,97.17 153.79,97.17 153.16,97.8 153.02,97.8 152.88,97.66 152.88,97.51 153.3,97.09 153.3,96.92 153.18,96.81 153.01,96.81 152.59,97.23 152.45,97.23 152.02,96.81 145.32,96.81 143.44,94.93 ; U25.7 216.6,122.57 214.91,120.89 214.45,120.89
  vias: v1(185.36,118.59)
M_A_DQ55: length 0.6
  TOP w0.076: 185.67,108.73 185.67,108.73 185.27,108.33
M_A_DQ61: length 0.6
  TOP w0.076: 189.67,103.93 189.67,103.84 189.99,103.53 190.05,103.53
M_A_ZQ1: length 8
  TOP w0.203: U15.L8 193.28,62.77 193.28,63.52
  TOP w0.254: 193.28,63.52 194.78,65.03 197.64,65.03 198.13,64.54 199.18,64.54
M_A_ZQ4: length 3.3
  TOP w0.203: U12.L8 193.28,109.13 193.28,110
  TOP w0.254: 193.28,110 194.58,111.3
M_B_A0: length 4.7
  BOTTOM w0.165: 165.04,82.12 165.55,81.61 167.86,81.61 168.3,82.05 JDIM6.98
M_B_A1: length 2.1
  BOTTOM w0.076: 138.96,75.99 138.96,76.05 138.62,76.38
  BOTTOM w0.165: 162.58,81.92 162.41,81.75 161.12,81.75
M_B_A2: length 4.3
  BOTTOM w0.076: 138.23,75.1 138.23,75.31 137.97,75.57
  BOTTOM w0.165: JDIM6.96 168.16,81.45 167.97,81.27 166.5,81.27 166.29,81.05 166.29,80.57
M_B_A5: length 2.9
  BOTTOM w0.165: 161.12,79.95 162.46,79.95 163.08,79.33 163.08,78.67
M_B_A7: length 3.5
  BOTTOM w0.165: JDIM6.86 168.23,78.45 167.35,77.57 166.92,77.57 166.51,77.17 166.51,77.01
M_B_A9: length 2.9
  BOTTOM w0.076: 140.11,72.18 140.11,72.34 U28.AU46
  BOTTOM w0.165: 161.12,78.15 162.08,78.15 162.98,77.24
M_B_A11: length 46.5
  IN1 w0.114: 144.96,71.77 144.85,71.66 143.77,71.66 v1(143.42,72.01)
  IN1 w0.178: v4(167.91,77.09) 170.04,77.09 171.23,78.28 173.27,78.28 173.54,78.02 173.54,76.13 173.33,75.92 170.6,75.92 170.46,75.78 165.72,75.78 165.06,75.12 160.29,75.12 158.81,73.65 157.99,73.65 154.98,70.64 147.36,70.64 146.24,71.77 144.96,71.77
  BOTTOM w0.076: v1(143.42,72.01) 142.91,71.5 140.94,71.5 140.65,71.79 140.43,71.79
  BOTTOM w0.165: v4(167.91,77.09) 167.91,77.65 168.11,77.85 JDIM6.84
M_B_BS#0: length 4.9
  BOTTOM w0.165: 165.5,86.64 164.21,85.35 161.12,85.35
M_B_CKE0: length 25.9
  IN1 w0.178: v4(163.06,73.26) 163.02,73.29 161.05,73.29 159.57,71.82 158.75,71.82 155.74,68.81 146.61,68.81 145.12,70.29 v1(144.15,70.29)
  BOTTOM w0.165: 161.12,74.55 162.12,74.55 162.42,74.25 162.42,73.94 162.27,73.79 161.74,73.79 161.59,73.63 161.59,73.41 161.74,73.26 v4(163.06,73.26)
M_B_CKE1: length 31.9
  IN1 w0.178: v1(142.84,70.28) 143.37,69.75 145.06,69.75 146.45,68.35 155.9,68.35 158.93,71.39 159.75,71.39 161.11,72.75 163.92,72.75 164.23,72.44 v4(168.67,72.44)
  BOTTOM w0.076: v1(142.84,70.28) 142.3,70.28 141.91,69.88 140.01,69.88 139.78,70.11
M_B_CLK0: length 4.9
  BOTTOM w0.102: 161.12,82.95 162.25,82.95 162.44,83.15 162.69,83.15 163.16,82.68 163.92,82.68 164.2,82.96 164.2,83.29 164.3,83.39 164.74,83.39 ; U28.AN38 137.65,77.55 v1(137.65,77.48)
M_B_CLK1: length 4.2
  BOTTOM w0.102: v4(167.68,82.09) 167.25,82.09 167.15,82.2 167.15,82.7 167.89,83.45 168.03,83.45 168.23,83.25 JDIM6.102 ; 136.02,77.88 136.35,77.56 v1(136.35,77.49)
M_B_CLK1#: length 4
  BOTTOM w0.102: JDIM6.104 168.19,83.85 168,83.65 167.81,83.65 166.95,82.79 166.95,82.2 166.83,82.08 166.41,82.08
M_B_DQ0: length 4.1
  BOTTOM w0.102: 164.84,61.08 163.91,60.15 161.12,60.15
M_B_DQ1: length 4.2
  BOTTOM w0.102: 138.62,65.11 138.68,65.11 138.95,64.83 138.95,64.66 ; 161.12,60.75 162.33,60.75 162.73,60.35 163.47,60.35 163.67,60.56 163.67,60.91 163.47,61.11 163.34,61.11
M_B_DQ3: length 46.4
  IN1 w0.076: v1(135.7,65.58) 135.31,65.19 135.31,63.72
  IN1 w0.114: 135.31,63.72 135.31,61.56 134.91,61.16 134.91,56.37 137.23,54.05 146.95,54.05 147.34,54.44 151.16,54.44 151.3,54.3 152.85,54.3 153.48,54.93 157.48,54.93 159.26,56.71 164.37,56.71 164.51,56.57 v4(164.51,55.98)
  BOTTOM w0.076: v1(135.7,65.58) 135.7,65.67 135.37,66.01
  BOTTOM w0.102: JDIM6.23 163.34,57.15 v4(164.51,55.98)
M_B_DQ4: length 2.2
  BOTTOM w0.076: 136.02,65.11 136.34,64.79 136.34,64.67
  BOTTOM w0.102: 169.32,57.45 168.15,57.45 167.81,57.79
M_B_DQ5: length 3.8
  BOTTOM w0.102: 166.23,57.76 166.23,57.2 166.59,56.85 169.32,56.85
M_B_DQ6: length 1.5
  BOTTOM w0.102: 167.8,61.08 167.82,61.05 169.32,61.05
M_B_DQ7: length 3.4
  BOTTOM w0.102: 169.32,60.45 166.81,60.45 166.18,61.08
M_B_DQ8: length 4
  BOTTOM w0.102: 161.12,61.95 163.87,61.95 164.74,62.82
M_B_DQ10: length 41.8
  IN1 w0.076: 142.72,64.52 139.24,68 137.6,68 v1(137,67.4)
  IN1 w0.114: v4(164.02,66.11) 164.31,66.11 164.43,66.23 164.43,66.41 164.31,66.53 162.39,66.53 161.63,65.77 158.9,63.05 156.93,63.05 156.15,62.26 150.85,62.26 150.3,61.72 145.75,61.72 144.97,62.5 144.8,62.5 144.1,61.8 143.93,61.8 143.81,61.93 143.81,62.1 144.5,62.8 144.5,62.96 144.37,63.09 144.2,63.09 143.43,62.32 143.26,62.32 143.14,62.44 143.14,62.62 143.91,63.39 143.91,63.55 143.77,63.68 143.61,63.68 143.48,63.56 143.31,63.56 143.19,63.68 143.19,63.85 143.32,63.98 143.32,64.14 142.94,64.52 142.72,64.52
  BOTTOM w0.076: U28.AM54 137,67.58 v1(137,67.4)
  BOTTOM w0.102: JDIM6.51 163.46,65.55 164.02,66.11 v4(164.02,66.11)
M_B_DQ12: length 2.6
  BOTTOM w0.102: JDIM6.41 162.11,62.55 162.35,62.31 162.91,62.31 163.44,62.84
M_B_DQ13: length 1.8
  BOTTOM w0.102: 167.63,66.11 167.89,65.85 169.32,65.85
M_B_DQ15: length 41.2
  IN1 w0.076: v1(137.66,67.41) 138.07,67.82 139.13,67.82 142.9,64.06
  IN1 w0.114: v4(162.55,66.11) 159.14,62.7 157.08,62.7 156.12,61.75 155.85,61.75 155.68,61.92 155.33,61.92 155.22,61.8 155.22,61.39 155.09,61.27 154.92,61.27 154.8,61.39 154.8,61.8 154.68,61.92 154.49,61.92 154.38,61.8 154.38,61.39 154.26,61.27 154.08,61.27 153.96,61.39 153.96,61.8 153.85,61.92 153.66,61.92 153.54,61.8 153.54,61.39 153.42,61.27 153.24,61.27 153.12,61.39 153.12,61.79 153,61.92 152.83,61.92 152.7,61.79 152.7,61.69 152.58,61.57 152.41,61.57 152.28,61.69 152.28,61.79 152.16,61.92 151.99,61.92 151.86,61.79 151.86,61.7 151.74,61.57 151.57,61.57 151.45,61.7 151.45,61.81 151.34,61.92 151.07,61.92 150.92,61.76 150.92,61.53 150.77,61.37 150.45,61.37 150.34,61.26 150.34,61 150.22,60.87 150.04,60.87 149.92,61 149.92,61.26 149.81,61.37 149.62,61.37 149.5,61.26 149.5,61 149.38,60.87 149.21,60.87 149.08,61 149.08,61.26 148.97,61.37 145.18,61.37 145.07,61.49 145.07,61.83 144.94,61.95 144.77,61.95 144.65,61.83 144.65,61.49 144.53,61.37 143.51,61.37 142.41,62.48 142.41,63.1 142.53,63.22 142.78,63.22 142.9,63.33 142.9,64.06
  BOTTOM w0.076: 137.32,67.9 137.66,67.57 v1(137.66,67.41)
  BOTTOM w0.102: JDIM6.53 162,66.15 162.42,66.58 162.78,66.58 162.91,66.45 162.91,66.19 162.82,66.11 v4(162.55,66.11)
M_B_DQ26: length 40
  IN1 w0.076: 142.36,66.78 140.07,69.06 139.16,69.06 138.32,69.91 137.15,69.91 v1(136.79,70.26)
  IN1 w0.114: 142.36,66.78 143.32,66.78 144.67,65.43 145.31,65.43 146.02,64.72 151.81,64.72 152.38,65.28 157.97,65.28 161.7,69.01 166.66,69.01 167.35,69.7 167.53,69.7 167.67,69.56 167.67,69.38 166.92,68.63 166.92,68.43 v4(167.15,68.2)
  BOTTOM w0.076: v1(136.79,70.26) 136.79,70.63 136.67,70.76
  BOTTOM w0.102: 169.32,67.65 167.7,67.65 v4(167.15,68.2)
M_B_DQ27: length 39.2
  IN1 w0.076: v1(135.57,70.26) 135.3,69.99 135.3,69.21 135.56,68.94 135.83,68.94 136.22,68.54 139.58,68.54 142.09,66.03
  IN1 w0.114: v4(164.35,68.23) 164.35,67.85 164.25,67.74 161.89,67.74 158.4,64.25 156.43,64.25 155.87,63.69 145.6,63.69 144.51,64.77 144.33,64.77 143.06,66.03 142.09,66.03
  BOTTOM w0.076: 135.37,70.78 135.57,70.58 v1(135.57,70.26)
  BOTTOM w0.102: 161.12,67.35 164.22,67.35 164.35,67.49 v4(164.35,68.23)
M_B_DQ28: length 5.6
  BOTTOM w0.076: 137,71.27 137,71.33 U28.AM48
  BOTTOM w0.102: 162.7,70.16 162.98,70.16 163.11,70.03 163.11,69.51 163.23,69.39 163.4,69.39 163.52,69.51 163.52,70.41 163.21,70.72 162.42,70.72 162.06,70.35 161.12,70.35
M_B_DQ29: length 3.4
  BOTTOM w0.102: 164.1,70.16 164.1,70.31 163.46,70.95 161.12,70.95
M_B_DQ31: length 3.3
  BOTTOM w0.102: JDIM6.59 162.19,67.95 162.59,67.55 163.06,67.55 163.27,67.76 163.27,68.05 163.06,68.25 162.75,68.25
M_B_DQ32: length 1.9
  BOTTOM w0.102: JDIM6.130 168.21,91.65 167.66,92.2
M_B_DQ35: length 1.8
  BOTTOM w0.102: 161.12,91.95 162.93,91.95 162.93,91.95
M_B_DQ42: length 4.3
  BOTTOM w0.076: 138.97,85.51 138.97,85.67 138.62,86.01
  BOTTOM w0.102: 164.25,99.37 164.25,99.54 163.39,100.41 162.2,100.41 162.14,100.35 JDIM6.159
M_B_DQ44: length 45.9
  IN1 w0.076: 149.95,90.04 149.69,90.04 146.53,86.88 144.58,86.88 142.91,85.21 141.97,85.21 141.44,84.69 141.44,84.25 141.33,84.14 141.1,84.14 141,84.24 141,84.44 140.91,84.53 140.7,84.53 140.63,84.46 140.63,83.86 140.52,83.75 140.36,83.75 140.25,83.86 140.25,84.46 140.17,84.53 139.97,84.53 139.77,84.33 139.77,84.15 139.89,84.02 139.89,83.85 139.79,83.75 139.56,83.75 139.49,83.82 139.49,83.9 139.39,84 138.04,84 137.84,84.2 135.86,84.2 135.7,84.36 v1(135.7,84.62)
  IN1 w0.114: v4(162.88,97) 162.88,97.36 163,97.48 165.23,97.48 165.36,97.6 165.36,97.78 165.23,97.9 162.81,97.9 162.53,97.62 162.11,97.62 162,97.73 162,98.07 161.87,98.19 161.7,98.19 161.58,98.07 161.58,97.74 161.46,97.62 161.28,97.62 161.16,97.74 161.16,98.07 161.04,98.19 160.86,98.19 160.74,98.07 160.74,97.73 160.63,97.62 158.72,97.62 158.15,97.05 157.62,97.05 150.62,90.04 149.95,90.04
  BOTTOM w0.076: U28.AK26 135.7,84.73 v1(135.7,84.62)
  BOTTOM w0.102: 161.12,96.75 162.63,96.75 v4(162.88,97)
M_B_DQ45: length 45.4
  IN1 w0.076: v1(137.02,84.62) 137.43,85.03 138.6,85.03 138.67,84.95 139.35,84.95 139.62,85.22 140.91,85.22 142.22,86.52 143.36,86.52 144.29,87.45 146.37,87.45 149.28,90.36 149.28,90.69 149.42,90.83
  IN1 w0.114: 149.42,90.83 149.66,91.07 150.19,91.07 157.2,98.08 157.72,98.08 158.29,98.64 159.82,98.64 160.4,99.22 162.37,99.22 162.66,98.93 169.51,98.93 169.71,98.73 169.71,97.25 169.51,97.05 v4(167.48,97.05)
  BOTTOM w0.076: 136.67,85.06 137.02,84.71 v1(137.02,84.62)
  BOTTOM w0.102: v4(167.48,97.05) JDIM6.148
M_B_DQ47: length 46
  IN1 w0.076: 146.9,91.64 146.6,91.64 143.32,88.37 141.95,88.37 140.04,86.46 137.49,86.46 137.08,86.04 136.78,86.04 v1(136.35,85.61)
  IN1 w0.114: v4(167.81,101.25) 169.98,101.25 170.15,101.41 170.15,101.64 169.98,101.8 167.68,101.8 167.22,102.26 165.78,102.26 165.57,102.05 158.86,102.05 158.39,101.58 157.46,101.58 149.67,93.79 149.67,93.55 147.77,91.64 146.9,91.64
  BOTTOM w0.076: 136.02,86.01 136.35,85.69 v1(136.35,85.61)
  BOTTOM w0.102: v4(167.81,101.25) 168.41,100.65 169.32,100.65
M_B_DQ48: length 42
  IN1 w0.076: 146.14,93.77 145.88,93.77 142.94,90.83 142,90.83 139.71,88.55 139.13,88.55 138.99,88.41 v1(138.99,88.32)
  IN1 w0.114: v4(162.73,106.05) 162.73,105.82 162.61,105.7 162.04,105.7 161.92,105.81 161.92,106.02 161.8,106.14 161.63,106.14 161.51,106.02 161.51,105.81 161.39,105.7 161.2,105.7 161.09,105.81 161.09,106.02 160.96,106.14 160.79,106.14 160.67,106.02 160.67,105.81 160.55,105.7 160.36,105.7 160.25,105.81 160.25,106.02 160.13,106.14 159.95,106.14 159.83,106.02 159.83,105.81 159.71,105.7 159.52,105.7 159.41,105.81 159.41,106.02 159.29,106.14 159.11,106.14 158.99,106.02 158.99,105.81 158.88,105.7 158.69,105.7 158.57,105.81 158.57,106.02 158.45,106.14 158.28,106.14 158.15,106.02 158.15,105.81 158.04,105.7 157.61,105.7 152.26,100.35 152.1,100.35 151.88,100.57 151.71,100.57 151.58,100.44 151.58,100.27 151.8,100.05 151.8,99.89 151.67,99.75 151.51,99.75 151.26,100 151.09,100 150.97,99.87 150.97,99.7 151.21,99.46 151.21,99.3 151.08,99.16 150.91,99.16 150.49,99.58 150.32,99.58 150.19,99.46 150.19,99.29 150.62,98.86 150.62,98.7 150.48,98.57 150.32,98.57 150.25,98.64 150.07,98.64 149.95,98.52 149.95,98.35 150.02,98.27 150.02,98.11 149.38,97.46 149.22,97.46 148.65,96.89 148.48,96.89 148.31,97.06 148.14,97.06 148.01,96.94 148.01,96.77 148.19,96.59 148.19,96.43 148.05,96.3 147.89,96.3 147.67,96.52 147.49,96.52 147.37,96.39 147.37,96.21 147.6,95.98 147.6,95.24 146.14,93.77
  BOTTOM w0.076: 138.62,88.76 138.62,88.68 138.99,88.31 v1(138.99,88.32)
  BOTTOM w0.102: JDIM6.177 162.43,105.75 v4(162.73,106.05)
M_B_DQ49: length 2.2
  BOTTOM w0.102: JDIM6.166 167.65,102.45 167.3,102.8
M_B_DQ57: length 47.3
  IN1 w0.076: v1(139.06,89.44) 139.54,89.44 140.76,90.65 140.89,90.65 142.38,92.15 142.38,92.58 143.78,93.98 143.78,94.11 144.57,94.9 144.88,94.9
  IN1 w0.114: v4(163.95,108.38) 164.9,108.38 165.04,108.25 165.04,108.05 164.9,107.91 163.75,107.91 163.53,107.69 162.25,107.69 162.14,107.81 162.14,108.42 162.02,108.53 160.34,108.53 160.21,108.41 160.21,108.23 160.34,108.11 161.59,108.11 161.71,107.99 161.71,107.81 161.59,107.69 157.35,107.69 153.67,104.01 153.31,104.01 153.18,103.89 153.18,103.73 153.24,103.68 153.24,103.52 153.1,103.38 152.94,103.38 152.89,103.43 152.73,103.43 152.41,103.12 152.25,103.12 151.97,103.4 151.81,103.4 151.68,103.27 151.68,103.1 152.02,102.76 152.02,102.55 151.87,102.41 151.66,102.41 151.38,102.69 151.1,102.69 150.85,102.44 150.85,102.28 150.95,102.18 150.95,102 150.83,101.88 150.66,101.88 150.48,102.06 150.29,102.06 148.64,100.42 148.64,99.86 145.75,96.97 145.75,95.77 144.88,94.9
  BOTTOM w0.076: 138.62,89.71 138.78,89.71 v1(139.06,89.44)
  BOTTOM w0.102: v4(163.95,108.38) 163.95,107.67 163.41,107.14 162.33,107.14 162.14,106.95 JDIM6.181
M_B_DQ59: length 48.8
  IN1 w0.114: v1(136.45,90.2) 136.18,90.47 136.18,91.16 136.34,91.31 136.52,91.31 136.64,91.19 136.64,91.06 136.74,90.96 137,90.96 137.35,91.31 139.26,91.31 139.67,91.72 139.67,92.43 139.92,92.69 140.53,92.69 140.76,92.91 140.76,93.89 142.66,95.79 142.89,95.79 143.06,95.95 143.06,96.3 143.46,96.7 143.46,96.93 143.46,98.41 145.82,100.77 145.82,101.76 148.2,104.14 148.2,104.39 148.4,104.6 148.66,104.6 148.83,104.78 148.83,105.03 149.05,105.24 149.21,105.24 149.44,105.01 149.62,105.01 149.74,105.13 149.74,105.31 149.51,105.54 149.51,105.7 149.72,105.92 149.93,105.92 150.11,105.74 150.36,105.74 150.92,106.3 151.07,106.3 151.18,106.41 151.18,106.89 151.3,107.01 151.48,107.01 151.6,106.89 151.6,106.42 151.72,106.3 151.9,106.3 152.02,106.42 152.02,106.97 152.14,107.09 152.32,107.09 152.44,106.97 152.44,106.44 152.56,106.32 152.74,106.32 152.86,106.44 152.86,106.97 152.98,107.09 153.51,107.09 157.24,110.82 157.52,110.82 157.62,110.92 157.62,111.2 157.76,111.34 157.93,111.34 158.05,111.22 158.05,110.93 158.16,110.82 158.33,110.82 158.47,110.96 158.47,111.27 158.59,111.39 163.57,111.39 163.7,111.25 163.7,111.06 163.57,110.92 v4(163.39,110.92)
  BOTTOM w0.102: v1(136.45,90.2) 136.45,90.2 136.45,90.26 136.05,90.67 136.02,90.67 ; JDIM6.193 163.02,110.55 v4(163.39,110.92)
M_B_DQ61: length 3.4
  BOTTOM w0.102: 169.32,110.25 167.75,110.25 167.56,110.44 166.64,110.44 166.16,110.92
M_B_DQ62: length 5
  BOTTOM w0.076: 138.62,90.67 138.65,90.67 139.01,90.31 139.01,90.31
  BOTTOM w0.102: 169.32,106.65 167.84,106.65 167.28,107.22 166.03,107.22 165.4,107.85
M_B_DQS0: length 44.2
  IN1 w0.114: v4(163.49,59.58) 164.07,59.58 164.18,59.48 164.18,59.06 164.06,58.94 162.21,58.94 161.61,58.35 158.88,58.35 156.89,56.35 151.82,56.35 151.33,55.86 148.17,55.86 148.08,55.95 148.08,56.11 147.84,56.35 147.47,56.35 147.23,56.11 147.23,55.93 147.16,55.86 146.53,55.86 146.14,55.47 138.28,55.47 136.94,56.81 136.94,61.79 137.38,62.23 137.38,64.49 137.6,64.72 v1(137.65,64.72)
  BOTTOM w0.076: 137.32,65.11 137.32,64.94 137.54,64.72 v1(137.65,64.72)
  BOTTOM w0.102: 161.12,58.95 162.25,58.95 162.46,58.74 163.88,58.74 164.15,59.01 164.15,59.46 164.04,59.58 v4(163.49,59.58)
M_B_DQS1: length 4.7
  BOTTOM w0.102: 161.12,64.35 162.14,64.35 162.34,64.15 162.64,64.15 163.12,63.67 164.3,63.67 164.44,63.81 164.44,64.2 164.34,64.3 163.84,64.3
M_B_DQS2: length 4.8
  BOTTOM w0.076: v1(136.29,75.07) 136.02,75.34 136.02,75.57
  BOTTOM w0.102: v4(165.86,52.64) 166.34,52.64 166.43,52.73 166.43,53.18 166.89,53.65 167.99,53.65 168.19,53.85 169.32,53.85
M_B_DQS7: length 4.3
  BOTTOM w0.102: 167.11,109.63 166.75,109.63 166.61,109.5 166.61,109.2 166.5,109.08 166.5,108.87 166.67,108.7 167.43,108.7 167.58,108.85 167.98,108.85 167.98,108.86 168,108.86 168.19,109.05 169.32,109.05
M_B_DQS#1: length 4.9
  BOTTOM w0.102: 161.12,63.75 162.14,63.75 162.34,63.95 162.57,63.95 163.04,63.48 164.38,63.48 164.63,63.73 164.63,64.16 164.79,64.31 165.11,64.31
M_B_DQS#2: length 3.8
  BOTTOM w0.102: 167.13,52.66 166.74,52.66 166.62,52.78 166.62,53.1 166.97,53.45 167.99,53.45 168.19,53.25 169.32,53.25
M_B_DQS#6: length 44
  IN1 w0.076: 146.87,93.96 146.86,93.95 146.86,93.91 146.4,93.45 145.81,93.45 142.91,90.55 142.05,90.55 139.42,87.92 138.56,87.92 138.54,87.95 137.93,87.95 v1(137.66,88.22)
  IN1 w0.114: 146.87,93.96 148.1,95.19 148.1,95.61 149.44,96.94 149.59,96.94 157.83,105.18 163.41,105.18 164,105.77 165.57,105.77 165.82,105.52 165.82,105.17 165.57,104.92 164.6,104.92 164.48,104.8 164.48,104.59 164.6,104.47 v4(165.06,104.47)
  BOTTOM w0.076: v1(137.66,88.22) 137.66,88.34 137.32,88.68 137.32,88.76
  BOTTOM w0.102: v4(165.06,104.47) 164.63,104.47 164.51,104.36 164.51,104.08 163.99,103.56 162.27,103.56 162.05,103.35 161.12,103.35
M_B_ODT0: length 1.2
  TOP w0.102: 135.66,81.23 135.65,81.24 135.65,81.54 TP45.1
M_B_RAS#: length 2.8
  BOTTOM w0.165: JDIM6.110 167.89,85.65 166.89,86.64
M_B_WE#: length 3.2
  BOTTOM w0.076: 135.37,79.79 135.69,79.47 135.69,79.35
  BOTTOM w0.165: 163.72,86.69 163.58,86.55 161.12,86.55
MDI_0-: length 1
  BOTTOM w0.102: 43.3,55.27 43.24,55.21 43.24,54.33
MDI_1+: length 1
  BOTTOM w0.102: 45.14,54.33 45.14,54.83 44.77,55.2
MDI_1-: length 1
  BOTTOM w0.102: U34.3 45.14,56.27 44.77,55.91
MDI_2+: length 5.5
  BOTTOM w0.102: U35.1 48.24,55.89 48.06,55.89 47.9,56.05 47.9,56.62 48.51,57.23 48.51,57.9 48.61,58 49.23,58 49.39,58.17 49.39,58.92
MDI_2-: length 0.9
  BOTTOM w0.102: 49.08,54.33 49.08,55.17 49.09,55.17
MDI_3+: length 8.1
  BOTTOM w0.102: 50.54,55.2 50.87,55.2 50.98,55.08 50.98,54.33 52.15,55.5 52.91,55.5 53.59,56.18 53.59,58.02 53.71,58.14 54.37,58.14 54.47,58.24 U30.1
MDI_3-: length 6.4
  BOTTOM w0.102: U30.2 53.2,56.34 52.75,55.88 51.82,55.88 U35.3 50.98,56.3 50.54,55.86
MX0: length 1.4
  BOTTOM w0.102: C569.2 194.57,48.02 194.81,48.26 ; 205.87,110.92 205.87,110.14
MY1: length 9.2
  TOP w0.102: 167.76,42.19 167.5,42.19 166.54,43.16 CP6.6
  BOTTOM w0.102: v1(211.01,113.31) 211.12,113.31 212.18,112.24 213.78,112.24 214.27,111.76 214.27,110.92 ; CN14.25 166.99,42.7 167.5,42.19 167.76,42.19
NOA_STBP_0: length 7.7
  BOTTOM w0.076: 130.5,60.92 130.5,61.69 130.49,61.69 130.49,62.93 U28.AA61
  BOTTOM w0.102: 130.5,60.92 130.5,60.32 129.68,59.51 129.68,56.21 129.86,56.03
NOA_STBP_1: length 13.8
  TOP w0.102: CN6.20 121.37,47.54 121.84,48 125.09,48 125.24,48.15 126.65,48.15 129.43,50.93 129.43,52.28 129.03,52.68 128.39,52.68 128.21,52.86
PCBEEP_EC:
  vias: v1(211.67,113.34)
PCH_BATLOW#: length 2.4
  BOTTOM w0.102: R505.1 140.45,105.45 140.45,104.37 140.12,104.04
PCH_BRIGHT: length 6.5
  BOTTOM w0.102: 119.75,95.62 119.02,95.62 118.13,96.52 116.76,96.52 116.45,96.22 115.38,96.22 115.1,95.94 ; 79.37,148.03 79.97,148.64 CN7.27
PCH_SLP_A#: length 1.4
  TOP w0.102: 140.33,106.83 140.33,106.2 140.2,106.07
  BOTTOM w0.102: 135.37,97.54 135.44,97.61 135.88,97.61
PCH_SLP_S5#: length 5.4
  TOP w0.102: v1(138.08,98.09) 138.08,97.91 138.35,97.64 140.33,97.64 141.72,99.04 TP32.1
  BOTTOM w0.102: v1(138.08,98.09) 137.83,97.84 137.83,97.61
PCH_SLP_WLAN#: length 2.4
  TOP w0.102: v1(136.47,98.16) 136.9,97.73 TP38.1
  BOTTOM w0.102: 136.53,97.61 136.47,97.68 v1(136.47,98.16)
PCH_SPI_CLK_EC: length 1.5
  BOTTOM w0.102: 206.87,125.25 206.87,125.7 206.67,125.9 206.67,126.62
PCH_SPI_SO: length 0.5
  BOTTOM w0.102: 131.2,98.87 130.89,98.56 130.78,98.56
PCH_SUSCLK: length 7.2
  TOP w0.102: 133.5,97.5 133.1,97.9 133.1,99.69 132.45,100.33 132.45,103.15 TP20.1
PCIE_IREF: length 1.1
  BOTTOM w0.203: 118.86,84.08 119.02,84.08 119.61,84.67 U28.B27
PCIE_RCOMP: length 2.9
  TOP w0.381: v1(118.25,84.08) 118.25,83.67 118.83,83.09 R232.1
  BOTTOM w0.254: U28.A27 118.78,84.67 118.25,84.15 v1(118.25,84.08)
PCIE_RX3+_LAN: length 0.9
  BOTTOM w0.102: 122.04,93.57 122.04,94.11 122.11,94.18 122.29,94.18 122.37,94.1
PEG_RX0: length 0.6
  BOTTOM w0.102: 121.4,94.59 121.4,94.73 121.72,95.06
PEG_RX2: length 0.7
  BOTTOM w0.102: 122.68,94.59 122.68,94.93 122.81,95.06 123.02,95.06
PEG_RX#2: length 0.6
  BOTTOM w0.102: 123.67,95.06 123.31,94.69 123.31,94.59
PEG_RX#3: length 0.6
  BOTTOM w0.102: U28.E6 121.72,96.75 122.03,96.45
R_PEG_TX1: length 6
  BOTTOM w0.102: U28.A23 118.99,87.21 118.7,87.21 118.43,86.95 116.87,86.95 116.62,87.2 116.35,87.2 v3(115.82,87.73) 115.82,87.23 115.69,87.1 114.8,87.1 114.68,87.22 C480.2
R_PEG_TX2: length 11.4
  BOTTOM w0.076: 118.68,88.79 118.69,88.78 118.69,88.75 118.74,88.7 119.29,88.7 119.63,88.37 119.87,88.37 120.03,88.53 120.8,88.53 U28.C21
  BOTTOM w0.102: 118.68,88.79 116.13,91.34 113.15,91.34 v3(112.59,91.9) 112.16,91.47 111.62,91.47 111.53,91.56 C463.2
R_PEG_TX3: length 6.5
  BOTTOM w0.076: 118.46,88.25 118.48,88.25 118.5,88.23 118.74,88.23 118.85,88.13 118.99,88.13 119.11,88.24
  BOTTOM w0.102: 118.46,88.25 118.14,88.25 116.58,89.82 115.99,89.82 115.87,89.94 v3(115.87,90.53) 115.28,89.94 114.8,89.94 114.68,90.06 C468.2
R_PEG_TX#1: length 6
  BOTTOM w0.102: U28.B23 119.31,87.06 119.27,87.02 118.8,87.02 118.52,86.74 116.79,86.74 116.53,87 116.35,87 v3(115.82,86.46) 115.38,86.9 114.82,86.9 114.68,86.75 C481.2
R_PEG_TX#3: length 6.6
  BOTTOM w0.076: 118.46,88.05 118.48,88.05 118.5,88.07 118.68,88.07 118.8,87.95 119.47,87.95 119.53,87.89 119.75,87.89
  BOTTOM w0.102: 118.46,88.05 118.06,88.05 116.5,89.61 115.99,89.61 115.87,89.49 v3(115.87,89.26) 115.38,89.74 114.85,89.74 114.68,89.57 C474.2
REGOUT: length 1.1
  BOTTOM w0.203: 30.98,50.98 31.13,50.83 U36.24
  vias: v3(28.26,50.88)
RING2:
  vias: v1(225.21,42.62) v1(225.21,42.01)
SENSOR_PCH_DAT: length 3.2
  BOTTOM w0.102: 217.52,112.97 216.72,112.97 216.53,113.17 215.14,113.17 214.6,113.72
SIO_A20GATE: length 3.6
  BOTTOM w0.102: U25.126 215.07,127.48 215.21,127.62 215.21,129.14 215.66,129.59 TP80.1
SMB_ME1_CLK: length 1.5
  TOP w0.102: R98.2 R97.2
SMB_ME1_DAT: length 6.9
  TOP w0.102: R92.2 145.65,121.02 144.94,120.31 Q14.1 ; R91.2 144.15,121.79 143.87,122.06 143.11,122.06 142.66,121.62 142.66,119.03
SUSB#: length 0.6
  BOTTOM w0.102: U28.AT4 139.35,98.32 139.35,98.09
SYS_PWROK_R: length 1.1
  BOTTOM w0.102: C571.2 R606.1
TESTLOW_AK8: length 0.6
  BOTTOM w0.102: 135.56,96.21 135.43,96.08 135.43,95.7
THRMTRIP#: length 1.6
  BOTTOM w0.102: R627.1 150.24,40.93 149.97,40.67 Q42.1
TP_DC_TEST_AV1: length 0.8
  TOP w0.102: 140.55,102.34 140.22,102.67 TP24.1
TP_PWR:
  vias: v1(78.35,150.27) v1(78.99,150.27)
TPD_EN: length 6.4
  BOTTOM w0.102: 34.41,41.48 35.5,41.48 35.72,41.26 CN17.8 35.72,36.29 35.7,36.27
TPM_RST_R: length 4.8
  TOP w0.102: U8.9 223.73,121.04 224.89,122.2 226.57,122.2 227.21,122.85
ULT_RVSD_62: length 11.3
  TOP w0.102: 122.93,64.92 122.57,64.57 122.57,62.71 122.11,62.26 118.56,62.26 115.59,59.29 TP54.1
ULT_RVSD_66: length 4.8
  TOP w0.102: v1(132.6,86.16) 133.21,85.55 133.21,83.34 TP44.1
  BOTTOM w0.102: v1(132.6,86.16) 132.05,86.71 132.05,87.23 132.22,87.4
ULT_RVSD_68: length 8.8
  TOP w0.102: v1(133.51,64.87) 133.51,64.68 136.41,61.77 136.41,58.55 TP64.1
  BOTTOM w0.102: 133.07,64.49 133.13,64.49 v1(133.51,64.87)
ULT_RVSD_70: length 5
  TOP w0.102: 126.65,63.53 127.35,62.84 127.35,59.96 126.73,59.34 TP52.1
ULT_RVSD_74: length 8.2
  TOP w0.102: TP69.1 133.16,58.12 133.16,63.01 v1(132.65,63.52)
  BOTTOM w0.127: 132.24,63.84 132.56,63.52 v1(132.65,63.52)
ULT_RVSD_77: length 7.5
  TOP w0.102: TP65.1 133.85,57.94 133.43,58.36 133.43,63.32 132.66,64.09 132.66,64.19
ULT_RVSD_78: length 7.6
  TOP w0.102: TP60.1 127.98,59.18 127.98,61.16 129.03,62.21 129.55,62.21 130.12,62.77 130.12,63.8 131.16,64.85
ULT_RVSD_80: length 7.3
  TOP w0.102: TP63.1 126.96,58.55 126.96,59.28 127.55,59.87 127.55,61.3 128.69,62.44 128.69,63.64 128.16,64.18
USB3_TXN0_C: length 1.7
  TOP w0.102: R329.2 13.43,24.45 13.43,24.63 C370.2
USB3_TXP0_C: length 1.7
  TOP w0.102: 12.69,23.91 13.22,24.45 13.22,24.63 C369.2
USBP5-_R: length 1.1
  BOTTOM w0.102: R380.1 92.06,144.06 ; 88.32,148.15 88.32,148.3 88.47,148.45 CN7.10
  vias: v3(92.27,145.82)
USBP6+_R: length 6
  BOTTOM w0.102: 88.29,144.92 88.61,145.24 88.61,145.49 88.41,145.7 v3(88.08,145.7) 88.61,146.23 88.61,146.4 87.74,147.27 87.39,147.27 86.61,148.06 86.61,148.36 86.47,148.5 CN7.14
USBP7+: length 0.6
  BOTTOM w0.102: CN11.16 225.7,50.55
VA1: length 2.7
  TOP w0.508: PD7.2 226.43,109.04 v1(226.99,108.49)
  vias: v3(227.45,109.5)
VA2:
  vias: v1(231.54,101.17) v1(231.54,99.98) v1(231.54,98.99)
VGA_VSSSENSE: length 0.8
  BOTTOM w0.356: 205.3,147.7 205.27,147.68 204.62,147.68 204.55,147.75
VREFC_VMA3: length 1
  TOP w0.508: 105.41,134.52 105.41,135.54
WRST#: length 4.3
  TOP w0.102: D14.2 219.65,112.68 220.35,113.37 220.91,113.37 221.22,113.68 R106.1 C139.1
XDP_BPM#6: length 7
  TOP w0.102: TP58.1 121.2,60.35 122.29,60.35 124.71,62.77 124.71,63.08 125.16,63.54
XDP_BPM#7: length 8.6
  TOP w0.102: v1(123.66,62.89) 122.53,61.75 119.24,61.75 117.59,60.1 TP56.1
  BOTTOM w0.127: v1(123.66,62.89) 123.96,63.19 124.08,63.19
XDP_PREQ#: length 2.5
  TOP w0.102: 126.48,54 125.87,53.39 125.87,51.79
XDP_RST_R_N: length 1.3
  TOP w0.102: CN6.8 115.37,44.79
XTAL24_OUT: length 0.3
  BOTTOM w0.102: C489.1 110.24,84.44
N05670:
  vias: v1(125.99,37.59) v3(112.89,41.81)
N243495: length 3.3
  BOTTOM w0.178: 226.86,91.43 226.56,91.73 226.56,94.31 226.79,94.54
N16780395:
  vias: v3(223.84,82.25)
N16789516:
  vias: v3(63.96,39.56)
N16789557:
  vias: v2(64.38,53.16) v2(64.35,51.92) v2(64.38,50.73) v2(64.35,49.43) v2(64.38,46.97) v2(65.24,53.6) v2(65.98,47.17) v2(66.13,48.64) v2(66.59,53.57) v2(67.12,48.64) v2(67.68,53.54) v2(68.09,48.62)
N16789582: length 0.9
  TOP w0.305: PU8.7 68.25,44.85
N16853944: length 2.4
  TOP w0.102: TP73.1 32.21,52.54 v1(32.88,52.54)
  BOTTOM w0.102: v1(32.88,52.54) 33.15,52.27 U36.26
N16876574: length 1.1
  TOP w0.102: PC21.1 182.57,129.06
N19870274:
  vias: v1(42.92,57.81) v1(43.68,57.81) v1(44.44,57.81) v1(50.54,57.81) v1(51.3,57.81) v1(52.06,57.81) v3(45.94,58.65)
N47340589: length 0.8
  TOP w0.102: U17.35 227.79,50.86 227.68,50.98 ; C303.2 231.13,54.81
N47341285: length 3.9
  TOP w0.102: 214.75,48.54 214.75,49.13 213.86,50.01 D18.1 D17.1
N47973729: length 0.9
  TOP w0.254: 175.3,125.83 174.9,125.43 PC23.2
N99212489: length 1.7
  TOP w0.102: v1(137.58,81.23) 136.92,81.89 TP46.1
  BOTTOM w0.076: v1(137.58,81.23) 137.97,81.62 137.97,81.69
N100631544: length 1.1
  BOTTOM w0.165: R544.1 R542.1
N101127130: length 1.4
  TOP w0.254: R136.1 144.65,108.76
N101265975:
  vias: v3(145.71,39.75)
N102031606: length 1.5
  TOP w0.508: R283.1 176.91,51.35 C327.2
N102803172: length 2.1
  BOTTOM w0.102: 202.17,125.63 203.19,125.63 203.47,125.91 203.47,126.62
N106398735: length 2.6
  TOP w0.305: 95.5,66.09 PR92.1
  BOTTOM w0.305: 95.5,66.09 95.14,65.73 93.99,65.73 PL13.3
N106398748: length 1.3
  BOTTOM w0.381: PR194.2 PR195.2
N106400425: length 2.7
  TOP w0.254: v1(96.84,75.13) 96.84,74.51
  BOTTOM w0.254: PL12.4 97.25,75.54 v1(96.84,75.13)
N106400429: length 1.7
  BOTTOM w0.254: PL12.3 95.17,75.54 95.47,75.24
N106400442: length 1.3
  BOTTOM w0.381: PR192.2 PR191.2
